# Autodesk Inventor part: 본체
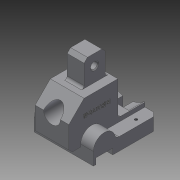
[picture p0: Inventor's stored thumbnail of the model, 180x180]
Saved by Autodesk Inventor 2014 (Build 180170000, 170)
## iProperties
Created: 2016-11
Part Number: 본체
Material: 일반
Document SubType Name: Modeling
Designer: USER
Density: 1 g/cm^3
Appearance: 기본값
Author: USER
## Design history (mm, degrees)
sketch "스케치1"
  geometry: L1 (63, 0)-(63, -15); L2 (63, -15)-(10, -15); L3 (10, -15)-(10, -8); L4 (10, -8)-(-10, -8); L5 (-10, -8)-(-10, -15); L6 (-10, -15)-(-13, -15); L7 (-13, -15)-(-13, 0); L8 (13, 0)-(63, 0); A1 r 13 centre (0, 0) between (13, 0) and (-13, 0); 1 further point
  constraints: 16 end point, 3 horizontal alignment, 3 parallel, 2 point on circle, 2 vertical alignment, 1 centre point, 1 coincident, 1 perpendicular, 1 tangent
  dimensions: "d1" = 26 diameter of A1; "d2" = 3 distance of L5.end L6.end; "d3" = 20 distance of L3.end L4.end; "d4" = 7 distance between parallel lines of L6 L4; "d5" = 63 distance from line of L1 point (0, 0); "d6" = 15 distance between parallel lines of L8 L2
extrude "돌출1" new body sketch "스케치1" stored distance "d7" = 70; taper "d8" = 0 deg
sketch "스케치2"
  geometry: L1 (63, -3)-(-27, -3); L2 (-27, -3)-(-27, 27); L3 (-27, 27)-(-9, 45); L4 (-9, 45)-(31, 45); L5 (31, 45)-(31, 5); L6 (31, 5)-(63, 5); L7 (63, 5)-(63, -3); L8 (63, -15)-(10, -15) reference; L9 (63, 0)-(63, -15) reference; L10 (-10, -15)-(-13, -15) reference; 1 further point
  constraints: 14 end point, 3 parallel, 2 vertical alignment, 1 horizontal, 1 perpendicular
  dimensions: "d9" = 48 distance between parallel lines of L4 L1; "d10" = 20 distance between parallel lines of L8 L6; "d11" = 45 deg angle of L4 L3; "d12" = 30 distance of L1.end L2.end; "d13" = 60 distance between parallel lines of L4 L10; "d14" = 58 distance between parallel lines of L5 L2; "d15" = 90 distance between parallel lines of L9 L2
extrude "돌출2" join sketch "스케치2" stored distance "d16" = 40; taper "d17" = 0 deg
sketch "스케치3"
  geometry: L1 (1, 41.207)-(26, 41.207); L2 (26, 41.207)-(26, 75); L3 (26, 75)-(1, 75); L4 (1, 75)-(1, 41.207); L5 (31, 45)-(31, 5) reference; L6 (63, -15)-(10, -15) reference; 1 further point
  constraints: 8 end point, 2 parallel, 1 horizontal, 1 perpendicular
  dimensions: "d18" = 25 distance of L2.end L3.end; "d19" = 5 distance between parallel lines of L5 L2; "d20" = 90 distance between parallel lines of L6 L3; "d21" = 33.79302 distance of L3.end L1.start
extrude "돌출3" join sketch "스케치3" stored distance "d22" = 20; taper "d23" = 0 deg
sketch "스케치5"
  geometry: L1 (55, 60)-(-15, 60) reference; 2 further points
  constraints: 1 vertical alignment
  dimensions: "d26" = 42 distance from line of L1 point (20, 18)
hole "구멍1" sketch "스케치5" at (20, 18) diameter "d27" = 20; stored, may be unused: countersink angle "d31" = 90 deg, drill point angle "d33" = 118 deg; dims "d28" = 6, "d29" = 29, "d30" = 7, "d32" = 8
sketch "스케치7"
  geometry: L1 (-75, 1)-(-45, 1) reference; L2 (-41.5, 31)-(-12.5, 31) reference; L3 (15, 63)-(15, 10) reference; C1 r 4 at (-62, 13.5); 1 further point
  constraints: 1 centre point
  dimensions: "d34" = 8 diameter of C1; "d35" = 12.5 distance from line of C1.centre L1; "d36" = 77 distance from line of L3 C1.centre
extrude "돌출4" cut sketch "스케치7" stored distance "d37" = 10; taper "d38" = 0 deg
sketch "스케치8"
  geometry: L1 (55, -20)-(15, -20) reference; L2 (41, 0)-(29, 0); L3 (29, 0)-(29, -13.627); L4 (41, -13.627)-(41, 0); C1 r 10 at (35, -42) reference; A1 r 29 centre (35, -42) between (53.894, -20) and (41, -13.627); A2 r 29 centre (35, -42) between (29, -13.627) and (16.106, -20); 3 further points
  constraints: 6 end point, 4 point on circle, 2 centre point, 2 point on line, 1 coincident, 1 horizontal, 1 horizontal alignment, 1 midpoint, 1 parallel, 1 perpendicular, 1 vertical alignment
  dimensions: "d40" = 12 distance of L2.start L2.end; "d41" = 29 radius of A1; "d42" = 29 radius of A2
extrude "돌출5" cut sketch "스케치8" distance "d43" = 18; taper "d44" = 0 deg
fillet "모깎기1" dims "d45" = 5
chamfer "모따기1" distance "d46" = 4; stored, may be unused: second distance "d47" = 2, angle "d48" = 45 deg
chamfer "모따기2" distance "d49" = 1; stored, may be unused: second distance "d50" = 2, angle "d51" = 45 deg
sketch "스케치9"
  geometry: L1 (0, 0)-(15, 0) reference; L2 (-14, -18)-(-14, 0) reference; L3 (15, 0)-(-14, 0) reference; L4 (15, -53)-(15, 0) reference; L5 (15, -53)-(-55, -53) reference; L6 (-55, 0)-(-55, -53) reference; L7 (-26, 0)-(-55, 0) reference; L8 (-26, 0)-(-26, -18) reference; L9 (-26, -18)-(-14, -18) reference; 3 further points
  dimensions: "d52" = 18 distance from line of L1 point (7.5, -18); "d53" = 18 distance from line of point (-47.5, -18) L7; "d54" = 55 distance of point (7.5, -18) point (-47.5, -18); "d55" = 7.5 distance from line of L6 point (-47.5, -18)
hole "구멍2" sketch "스케치9" at (7.5, -18), (-47.5, -18) diameter "d56" = 3.242; stored, may be unused: countersink angle "d60" = 90 deg, drill point angle "d62" = 118 deg; dims "d57" = 6, "d58" = 29, "d59" = 7, "d61" = 8
chamfer "모따기3" distance "d63" = 5; stored, may be unused: second distance "d64" = 2, angle "d65" = 45 deg
sketch "스케치10"
  geometry: L1 (-5, 31)-(-45, 31) reference; L2 (-45, 31)-(-45, -9) reference; 1 further point
  constraints: 1 other
  dimensions: "d66" = 25 distance from line of point (-27, 6) L1; "d67" = 18 distance from line of point (-27, 6) L2
feature "엠보싱1" sketch "스케치10" dims "d68" = 0.5, "d69" = 0
fillet "모깎기2" dims "d70" = 3
node "솔리드1"
node "투영된 루프1"
other parameters: "d39" = 58
